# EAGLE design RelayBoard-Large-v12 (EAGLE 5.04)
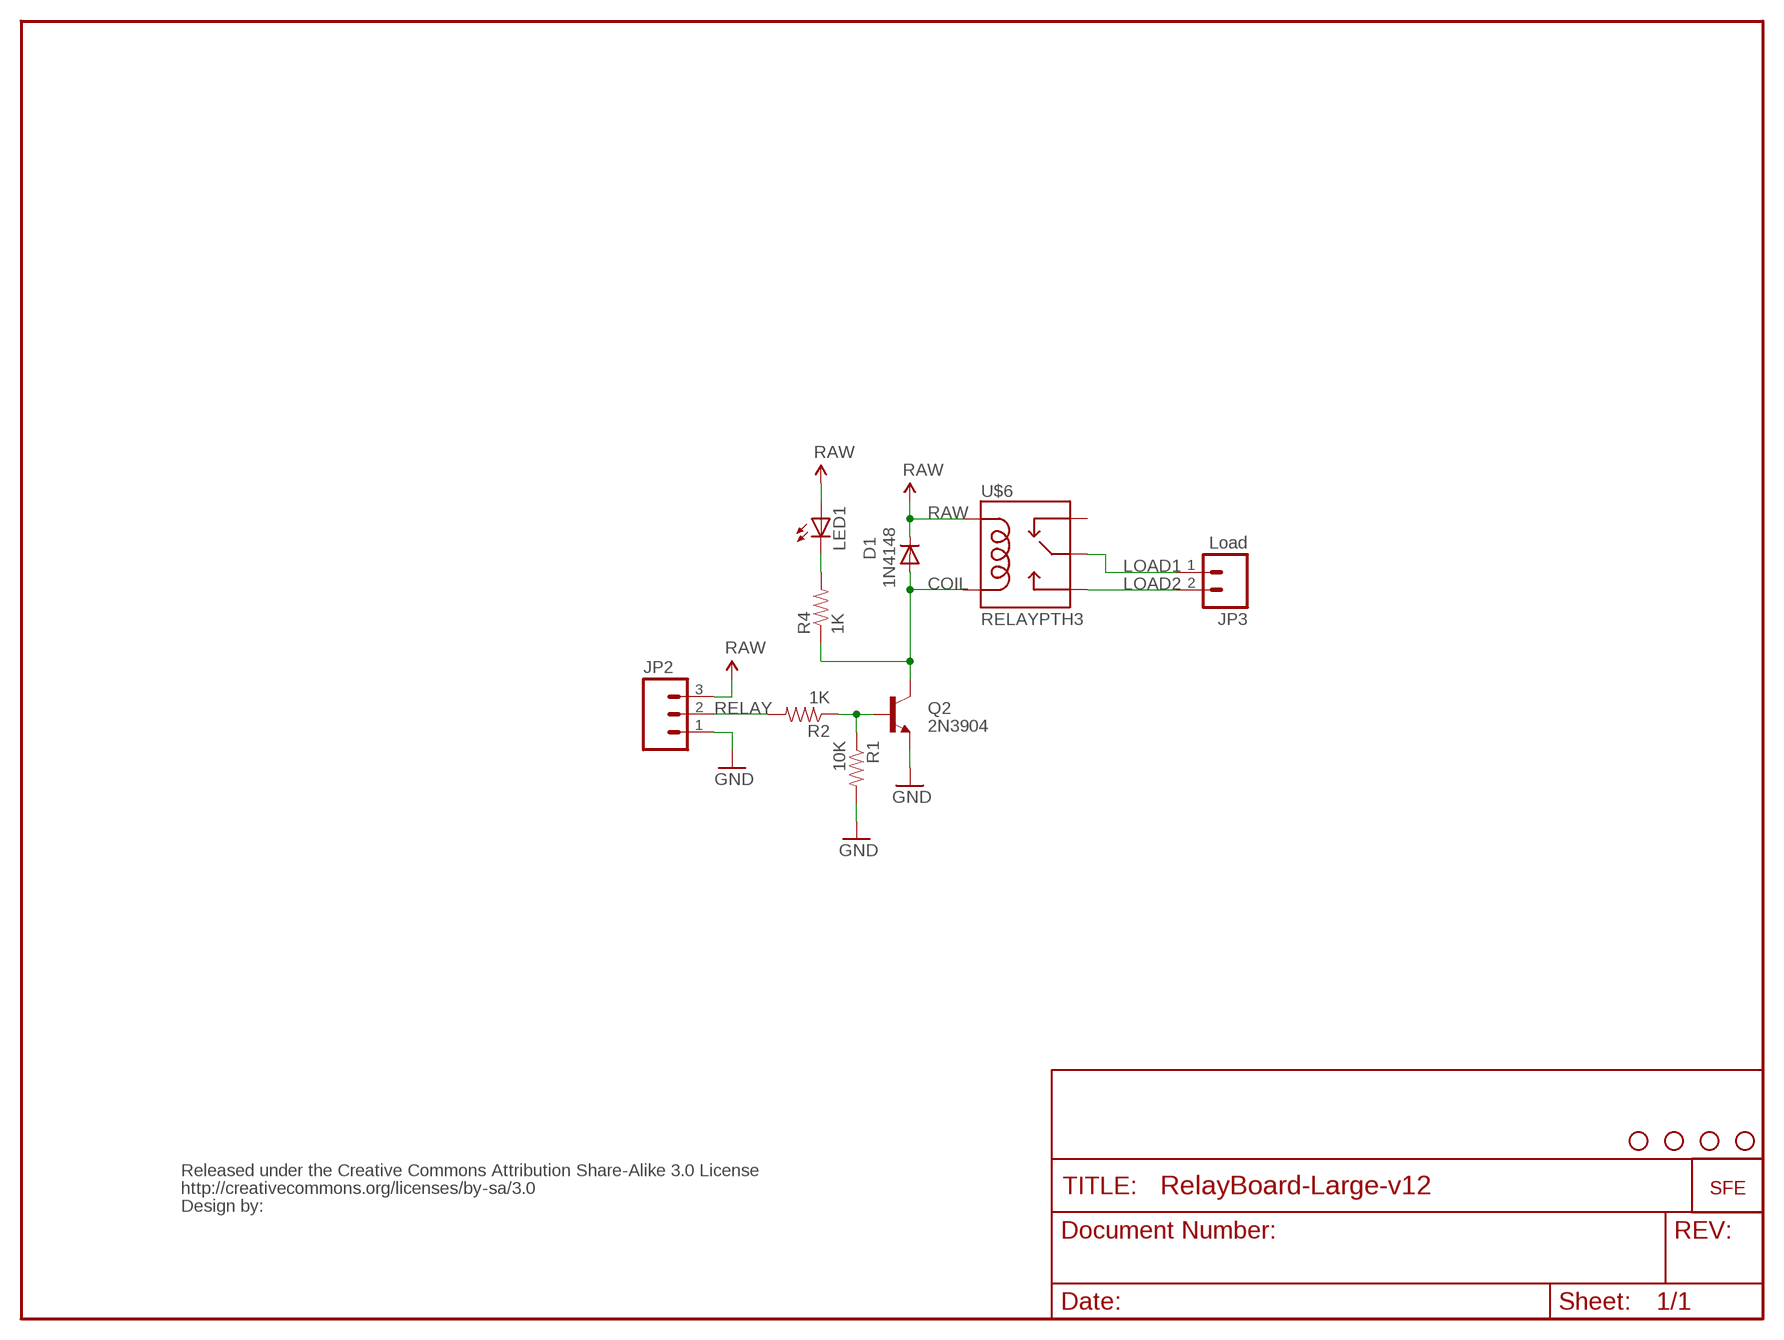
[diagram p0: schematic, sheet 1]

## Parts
D1  1N4148  DIODE1N4148  [DIODE-1N4148]
JP2  M03SCREW  [SCREWTERMINAL-3.5MM-3]
JP3  Load  M025MM  [SCREWTERMINAL-5MM-2]
LED1  LED5MM  [LED5MM]
Q2  2N3904  TRANSISTOR_NPNTO92  [TO-92]
R1  10K  RESISTORPTH1  [AXIAL-0.3]
R2  1K  RESISTORPTH1  [AXIAL-0.3]
R4  1K  RESISTORPTH1  [AXIAL-0.3]
U$1  LOGO-SFENEW  [SFE-NEW-WEBLOGO]
U$3  STAND-OFF  [STAND-OFF]
U$4  STAND-OFF  [STAND-OFF]
U$5  STAND-OFF  [STAND-OFF]
U$6  RELAYPTH3  [RELAY-T9A-2]
U$7  STAND-OFF  [STAND-OFF]
U$9  CREATIVE_COMMONS  [CREATIVE_COMMONS]

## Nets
COIL: D1.A Q2.3(C) R4.P$1 U$6.COIL2
GND: JP2.1 Q2.1(E) R1.P$2
LOAD1: JP3.1 U$6.MAIN
LOAD2: JP3.2 U$6.NO
N$6: Q2.2(B) R1.P$1 R2.P$1
N$9: LED1.K(C) R4.P$2
RAW: D1.C JP2.3 LED1.A U$6.COIL1
RELAY: JP2.2 R2.P$2
Unconnected: U$6.NC

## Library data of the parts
D1 = SparkFun:DIODE: Diode
JP2 = SparkFun:M03: Header 3 Standard 3-pin 0.1" header. Use with straight break away headers (SKU : PRT-00116), right angle break away headers (PRT-00553), swiss pins (PRT-00743), machine pins (PRT-00117), and female headers (PRT-00115). Molex polarized connector foot print use with SKU : PRT-08232 with associated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
JP3 = SparkFun:M02: Header 2
LED1 = SparkFun:LED: LEDs
Q2 = SparkFun:TRANSISTOR_NPN: Transistor NPN BJT configuration in SOT23 package. MMBT2222 is the common NPN we use. Double check BCE configuration again layout.
R1 R2 R4 = SparkFun:RESISTOR: Resistor
U$1 = SparkFun:LOGO-SFE: Spark Fun Electronics PCB Logo
U$3-U$5 U$7 = SparkFun:STAND-OFF: Stand Off
U$6 = SparkFun:RELAY
U$9 = SparkFun:CREATIVE_COMMONS

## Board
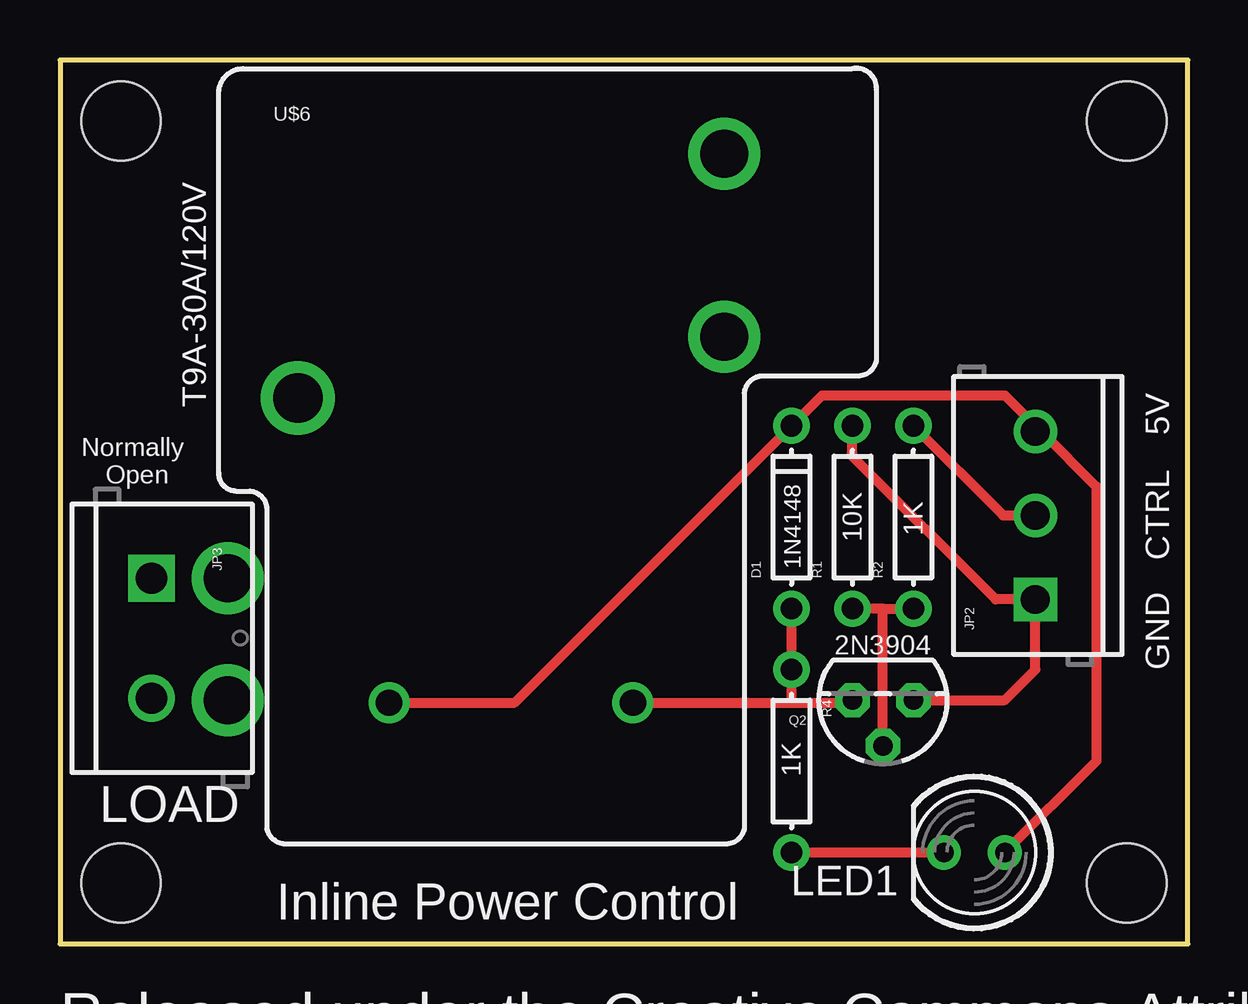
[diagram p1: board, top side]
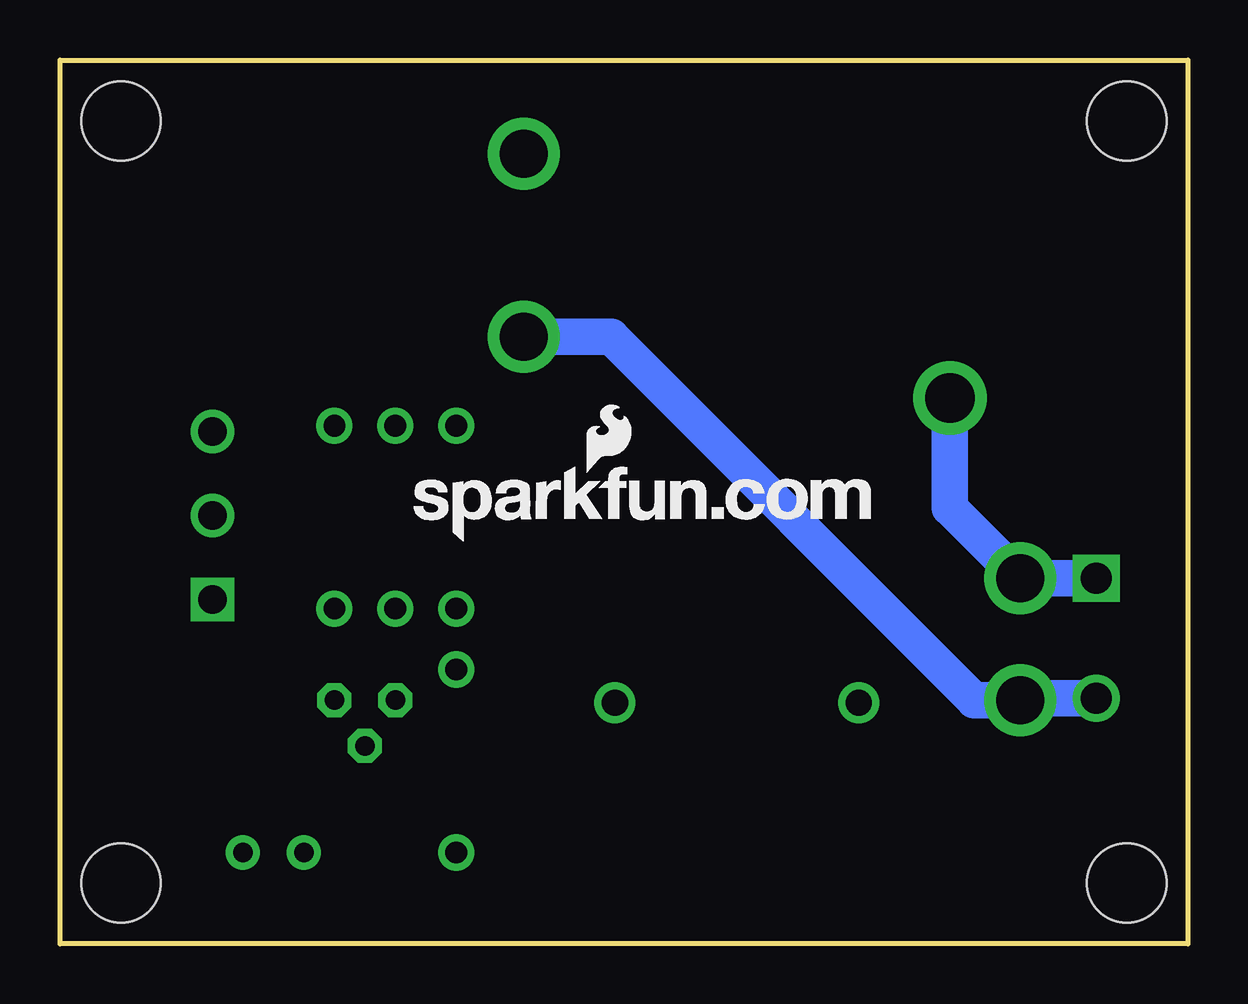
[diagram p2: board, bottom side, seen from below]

Size 46.99 x 36.83 mm. Coordinates in mm from the lower left corner, seen from the top.
Outline: 0,0 46.99,0 46.99,36.83 0,36.83 0,0
Copper layers (1*16): Top 0.035mm / dielectric 1.5mm / Bottom 0.035mm
Design rules "SparkFun *": minimum track width 16mil, minimum drill 20mil, track to track 8mil, track to pad 8mil, pad to pad 8mil, via to via 8mil, smd to smd 8mil, copper to edge 10mil, drill to drill 8mil, minimum pad ring 12mil, minimum via ring 10mil, stop-mask expansion 4mil, vias tented up to drill 20mil, thermal gap 10mil

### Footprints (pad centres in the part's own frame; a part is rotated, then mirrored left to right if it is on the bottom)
DIODE-1N4148 = drill 0.9 round: A -3.81,0; C 3.81,0
SCREWTERMINAL-3.5MM-3 = drill 1.2 square: 1 0,0 | drill 1.2 round: 2 3.5,0; 3 7,0
SCREWTERMINAL-5MM-2 = drill 1.3 square: 1 0,0 | drill 1.3 round: 2 5,0
LED5MM = drill 0.813 round: A -1.27,0; K 1.27,0
TO-92 = drill 0.813 octagon: 1 -1.27,0; 2 0,1.905; 3 1.27,0
AXIAL-0.3 = drill 0.9 round: P$1 -3.81,0; P$2 3.81,0
STAND-OFF = hole 3.302: 0,0
RELAY-T9A-2 = drill 1.1 round: COIL1 -6.61,-10.27; COIL2 3.55,-10.27 | drill 2.057 round: MAIN -10.41,2.43 | drill 2 round: NC 7.35,12.6; NO 7.35,4.97

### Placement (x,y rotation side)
D1  30.48,17.78 90 top
JP2  40.64,14.35 90 top
JP3  3.81,15.24 270 top
LED1  38.1,3.81 180 top
Q2  34.29,10.16 180 top
R1  33.02,17.78 90 top
R2  35.56,17.78 90 top
R4  30.48,7.62 270 top
U$1  32.26,16.76 0 bottom
U$3  2.54,2.54 0 top
U$4  44.45,2.54 0 top
U$5  44.45,34.29 0 top
U$6  20.32,20.32 0 top
U$7  2.54,34.29 0 top
U$9  not placed on the board

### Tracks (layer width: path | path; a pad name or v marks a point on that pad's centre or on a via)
COIL
  Top 0.406: U$6.COIL2 30.48,10.05 | D1.A R4.P$1 30.48,10.05 | 30.48,10.05 32.91,10.05 Q2.3
GND
  Top 0.406: Q2.1 39.37,10.16 40.64,11.43 JP2.1 38.99,14.35 33.02,20.32 R1.P$2
LOAD1  (via drill 2)
  Bottom 1.524: U$6.MAIN 9.91,18.16 v6.99,15.24 | v6.99,15.24 7.11,15.24 | JP3.1 v6.99,15.24
LOAD2  (via drill 2)
  Bottom 1.524: U$6.NO 24.02,25.29 8.89,10.16 v6.99,10.16 6.99,10.29 6.94,10.24 JP3.2
N$6
  Top 0.406: 34.29,13.97 R1.P$1 | 34.29,13.97 R2.P$1 | Q2.2 34.29,13.97
N$9
  Top 0.406: R4.P$2 LED1.K
RAW
  Top 0.406: LED1.A 43.18,7.62 43.18,19.05 40.88,21.35 JP2.3 40.64,21.59 39.37,22.86 31.75,22.86 D1.C 18.94,10.05 U$6.COIL1
RELAY
  Top 0.406: JP2.2 39.3,17.85 R2.P$2

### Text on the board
tPlace: T9A-30A/120V | 5V | Normally | Open | CTRL | GND | LOAD | Inline Power Control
